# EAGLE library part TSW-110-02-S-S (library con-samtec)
THROUGH-HOLE .025" SQ POST HEADER Source: Samtec TSW.pdf
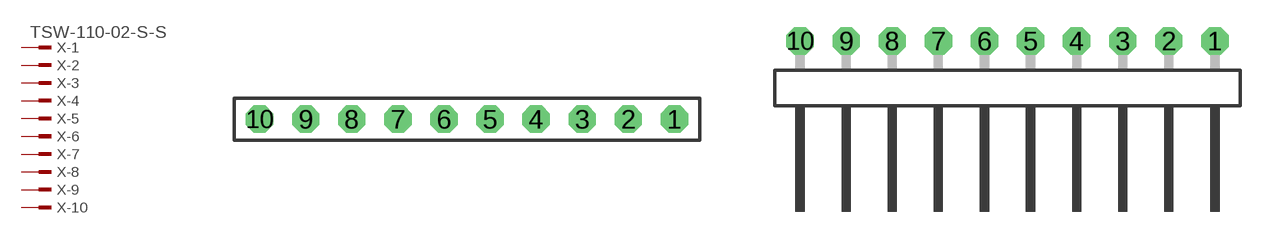
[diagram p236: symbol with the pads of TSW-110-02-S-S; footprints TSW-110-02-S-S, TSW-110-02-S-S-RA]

Designator prefix X; gates -1=MPINV -2=MPIN -3=MPIN -4=MPIN -5=MPIN -6=MPIN -7=MPIN -8=MPIN -9=MPIN -10=MPIN

## TSW-110-02-S-S (OC_FARNELL: unknown; OC_NEWARK: unknown)  [TSW-110-02-S-S]
1  -1:1  pas
2  -2:1  pas
3  -3:1  pas
4  -4:1  pas
5  -5:1  pas
6  -6:1  pas
7  -7:1  pas
8  -8:1  pas
9  -9:1  pas
10  -10:1  pas

## TSW-110-02-S-S-RA (OC_FARNELL: unknown; OC_NEWARK: unknown)  [TSW-110-02-S-S-RA]
Pads as for TSW-110-02-S-S

## Footprint TSW-110-02-S-S (pad centres in mm)
THROUGH-HOLE .025" SQ POST HEADER Source: Samtec TSW.pdf
drill 1 pad 1.5 octagon: 1 11.43,0; 2 8.89,0; 3 6.35,0; 4 3.81,0; 5 1.27,0; 6 -1.27,0; 7 -3.81,0; 8 -6.35,0; 9 -8.89,0; 10 -11.43,0

## Footprint TSW-110-02-S-S-RA (pad centres in mm)
THROUGH-HOLE .025" SQ POST HEADER Source: Samtec TSW.pdf
drill 1 pad 1.5 octagon: 1 11.43,1.524; 2 8.89,1.524; 3 6.35,1.524; 4 3.81,1.524; 5 1.27,1.524; 6 -1.27,1.524; 7 -3.81,1.524; 8 -6.35,1.524; 9 -8.89,1.524; 10 -11.43,1.524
